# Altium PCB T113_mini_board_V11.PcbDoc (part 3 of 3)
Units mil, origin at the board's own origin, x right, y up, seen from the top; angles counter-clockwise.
Board outline 2716.54 x 2716.54 mil, 4 copper layers (Top Layer, GND, PWR, Bottom Layer); 97 components, 127 nets, 497 pads, 287 vias.
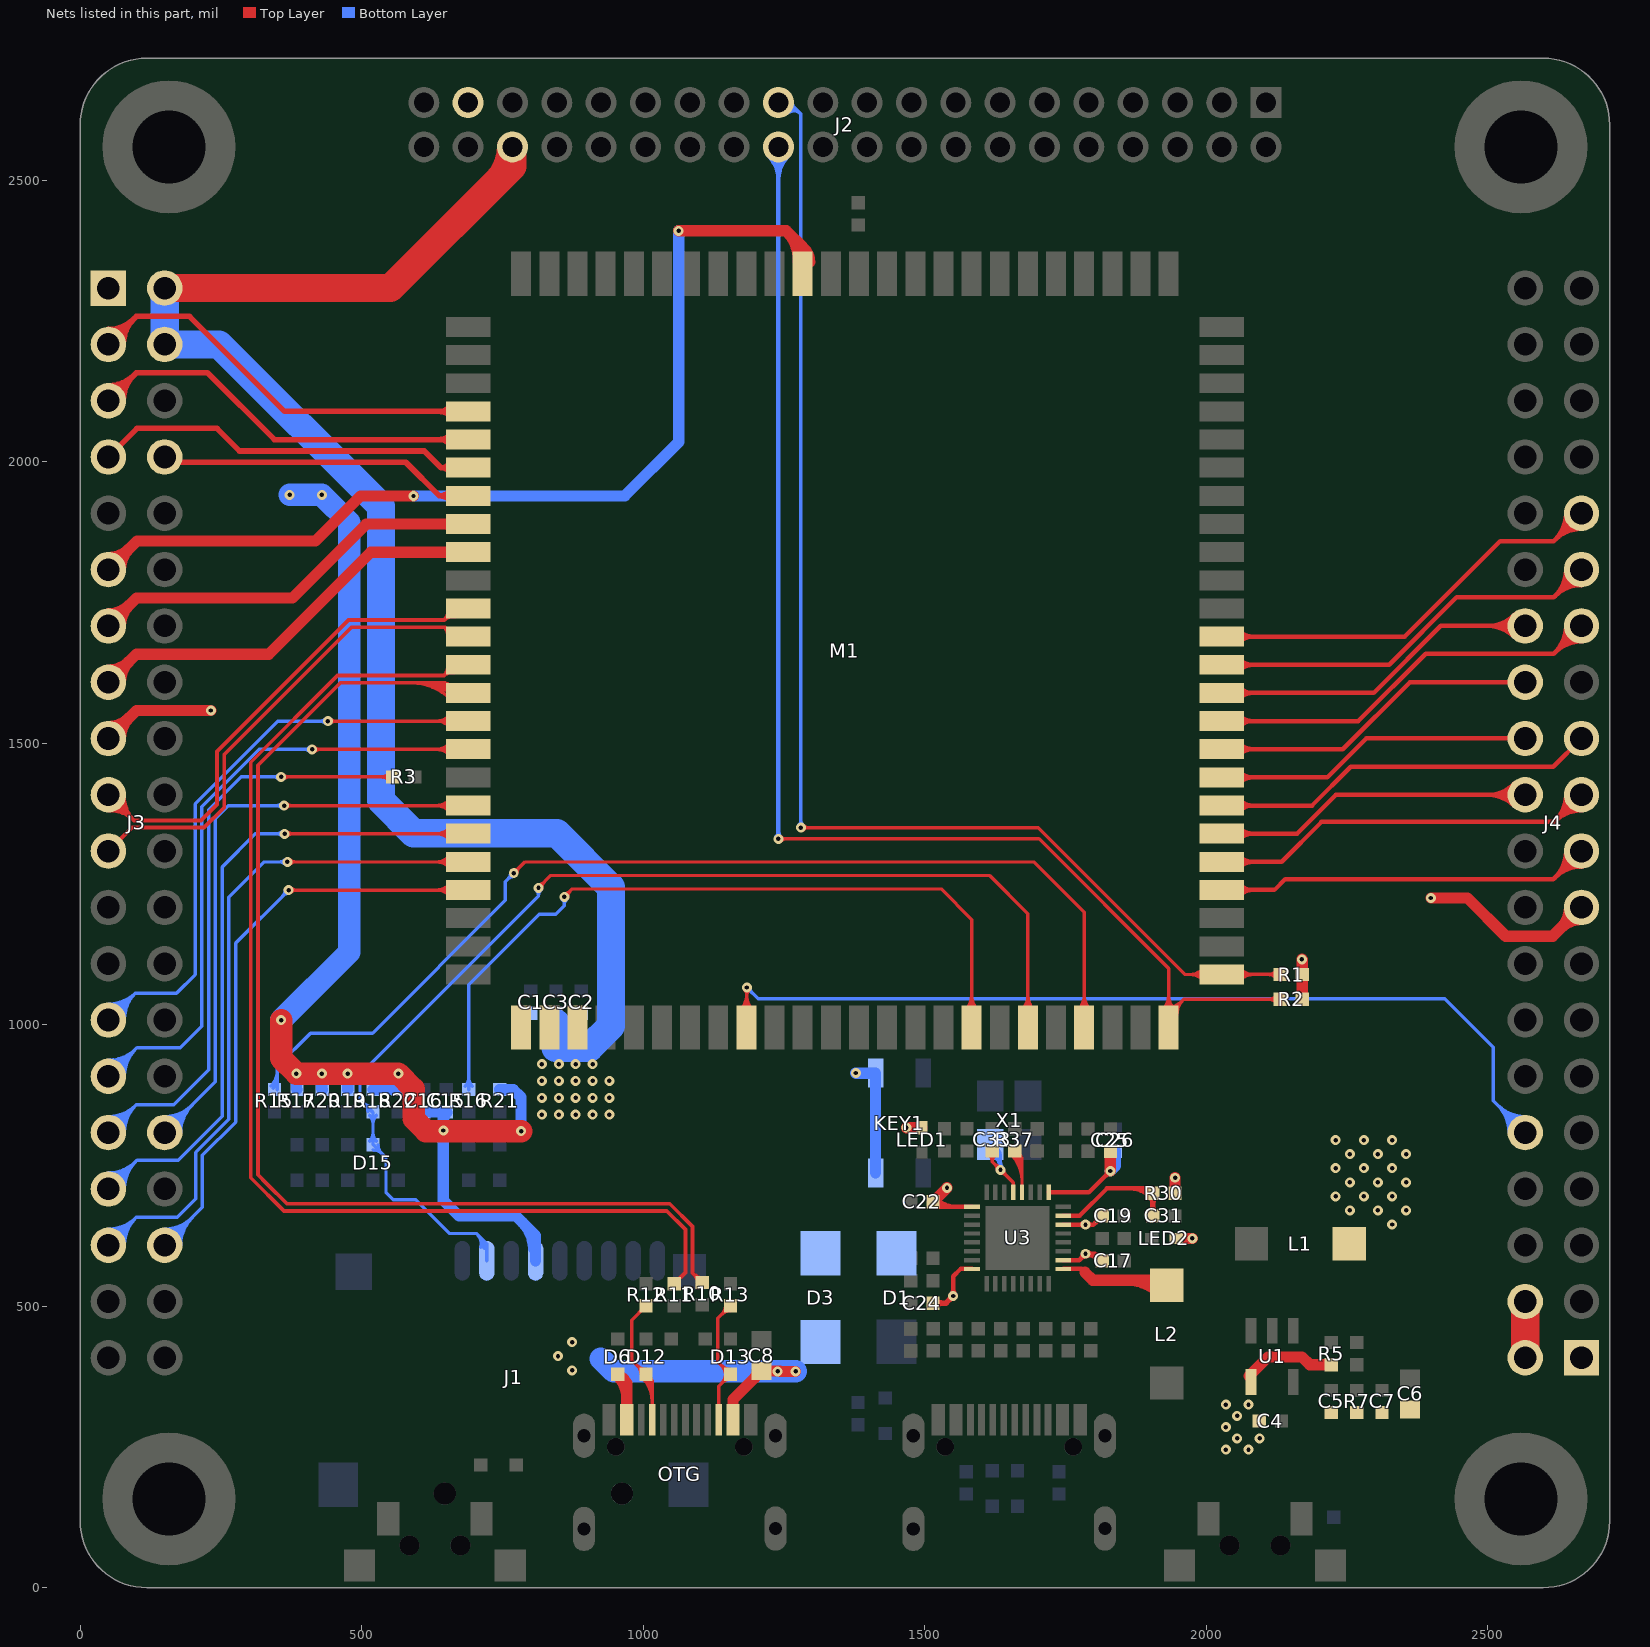
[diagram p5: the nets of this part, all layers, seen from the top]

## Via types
v1: diameter 17.72, hole 7.87, Top Layer to Bottom Layer, tented both sides, 278 vias
v2: diameter 23.62, hole 11.81, Top Layer to Bottom Layer, tented both sides, 9 vias

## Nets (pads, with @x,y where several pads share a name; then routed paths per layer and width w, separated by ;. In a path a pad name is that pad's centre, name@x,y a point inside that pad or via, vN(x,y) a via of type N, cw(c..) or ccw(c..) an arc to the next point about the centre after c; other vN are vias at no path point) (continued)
PE0: J4.29 M1.36 | length 939.2
  Top Layer w8: M1.36@2027.56,1639.21 2324.84,1639.21 2444.63,1759 2617.27,1759 J4.29@2666.54,1808.27 ; M1.36@2058.91,1629.51 cw(c2082.33,1606.1) 2082.33,1639.21 cw(c2082.33,1672.33) M1.36@2058.91,1648.91 ; J4.29@2639.04,1808.27 cw(c2572.66,1808.27) 2619.6,1761.33 cw(c2666.54,1714.39) J4.29@2666.54,1780.77 ; J4.29@2647.04,1808.27 cw(c2599.97,1808.27) 2633.25,1774.99 cw(c2666.54,1741.7) J4.29@2666.54,1788.77
PE1: J4.31 M1.37 | length 959.9
  Top Layer w8: M1.37@2027.56,1689.21 2352.21,1689.21 2522,1859 2617.27,1859 J4.31@2666.54,1908.27 ; M1.37@2058.91,1679.51 cw(c2082.33,1656.1) 2082.33,1689.21 cw(c2082.33,1722.33) M1.37@2058.91,1698.91 ; J4.31@2639.04,1908.27 cw(c2572.66,1908.27) 2619.6,1861.33 cw(c2666.54,1814.39) J4.31@2666.54,1880.77 ; J4.31@2647.04,1908.27 cw(c2599.97,1908.27) 2633.25,1874.99 cw(c2666.54,1841.7) J4.31@2666.54,1888.77
PE4: J4.28 M1.35 | length 818.5
  Top Layer w8: M1.35@2027.56,1589.21 2297.47,1589.21 2416.52,1708.27 J4.28@2566.54,1708.27 ; M1.35@2058.91,1579.51 cw(c2082.33,1556.1) 2082.33,1589.21 cw(c2082.33,1622.33) M1.35@2058.91,1598.91 ; J4.28@2547.09,1688.83 ccw(c2500.15,1641.89) 2500.15,1708.27 ccw(c2500.15,1774.65) J4.28@2547.09,1727.71 ; J4.28@2552.75,1694.48 ccw(c2519.47,1661.2) 2519.47,1708.27 ccw(c2519.47,1755.34) J4.28@2552.75,1722.05
PE5: J4.27 M1.34 | length 939.2
  Top Layer w8: M1.34@2027.56,1539.21 2270.09,1539.21 2389.88,1659 2617.27,1659 J4.27@2666.54,1708.27 ; M1.34@2058.91,1529.51 cw(c2082.33,1506.1) 2082.33,1539.21 cw(c2082.33,1572.33) M1.34@2058.91,1548.91 ; J4.27@2639.04,1708.27 cw(c2572.66,1708.27) 2619.6,1661.33 cw(c2666.54,1614.39) J4.27@2666.54,1680.77 ; J4.27@2647.04,1708.27 cw(c2599.97,1708.27) 2633.25,1674.99 cw(c2666.54,1641.7) J4.27@2666.54,1688.77
PE6: J4.26 M1.33 | length 640.3
  Top Layer w8: M1.33@2027.56,1489.21 2242.72,1489.21 2361.78,1608.27 J4.26@2566.54,1608.27 ; M1.33@2058.91,1479.51 cw(c2082.33,1456.1) 2082.33,1489.21 cw(c2082.33,1522.33) M1.33@2058.91,1498.91
PE7: J4.24 M1.32 | length 619.6
  Top Layer w8: M1.32@2027.56,1439.21 2215.35,1439.21 2284.4,1508.27 J4.24@2566.54,1508.27 ; M1.32@2058.91,1429.51 cw(c2082.33,1406.1) 2082.33,1439.21 cw(c2082.33,1472.33) M1.32@2058.91,1448.91
PE8: J4.23 M1.31 | length 740.3
  Top Layer w8: M1.31@2027.56,1389.21 2187.98,1389.21 2256.76,1458 2616.27,1458 J4.23@2666.54,1508.27 ; M1.31@2058.91,1379.51 cw(c2082.33,1356.1) 2082.33,1389.21 cw(c2082.33,1422.33) M1.31@2058.91,1398.91
PE9: J4.22 M1.30 | length 797.8
  Top Layer w8: M1.30@2027.56,1339.21 2161.21,1339.21 2230,1408 2566.27,1408 J4.22@2566.54,1408.27 ; M1.30@2058.91,1329.51 cw(c2082.33,1306.1) 2082.33,1339.21 cw(c2082.33,1372.33) M1.30@2058.91,1348.91 ; 2499.51,1408 ccw(c2499.51,1475.3) J4.22@2547.09,1427.71 ; 2500.8,1408 cw(c2500.8,1342.53) J4.22@2547.09,1388.83 ; 2518.82,1408 ccw(c2518.82,1455.98) J4.22@2552.75,1422.05 ; 2520.11,1408 cw(c2520.11,1361.85) J4.22@2552.75,1394.48
PE10: J4.21 M1.29 | length 918.5
  Top Layer w8: M1.29@2027.56,1289.21 2133.84,1289.21 2204.63,1360 2618.27,1360 J4.21@2666.54,1408.27 ; M1.29@2058.91,1279.51 cw(c2082.33,1256.1) 2082.33,1289.21 cw(c2082.33,1322.33) M1.29@2058.91,1298.91 ; J4.21@2639.04,1408.27 cw(c2572.66,1408.27) 2619.6,1361.33 cw(c2666.54,1314.39) J4.21@2666.54,1380.77 ; J4.21@2647.04,1408.27 cw(c2599.97,1408.27) 2633.25,1374.99 cw(c2666.54,1341.7) J4.21@2666.54,1388.77
PE11: J4.19 M1.28 | length 897.8
  Top Layer w8: M1.28@2027.56,1239.21 2121.21,1239.21 2140,1258 2616.27,1258 J4.19@2666.54,1308.27 ; M1.28@2058.91,1229.51 cw(c2082.33,1206.1) 2082.33,1239.21 cw(c2082.33,1272.33) M1.28@2058.91,1248.91 ; J4.19@2639.04,1308.27 cw(c2572.66,1308.27) 2619.6,1261.33 cw(c2666.54,1214.39) J4.19@2666.54,1280.77 ; J4.19@2647.04,1308.27 cw(c2599.97,1308.27) 2633.25,1274.99 cw(c2666.54,1241.7) J4.19@2666.54,1288.77
PE12: J2.23 M1.25 R1.1 | length 2625.3
  Top Layer w6: v1(1280,1350) 1702,1350 1963,1089 M1.25@2027.56,1089 ; v1@1284.14,1345.86 cw(c1294.14,1335.86) 1294.14,1350 cw(c1294.14,1364.14) v1@1284.14,1354.14 ; 1969.86,1089 ccw(c1969.86,1125.25) M1.25@1995.5,1099.62 ; 1970.89,1089 cw(c1970.89,1054.2) M1.25@1995.5,1078.81 ; 1984.35,1089 ccw(c1984.35,1110.77) M1.25@1999.74,1095.38 ; 1985.38,1089 cw(c1985.38,1068.68) M1.25@1999.74,1083.05 ; M1.25@2027.56,1089.21 2131.1,1089.21 R1.1@2131.32,1089 ; M1.25@2055.38,1083.05 cw(c2070.26,1068.17) 2070.26,1089.21 cw(c2070.26,1110.26) M1.25@2055.38,1095.38 ; M1.25@2059.62,1078.81 cw(c2084.74,1053.68) 2084.74,1089.21 cw(c2084.74,1124.74) M1.25@2059.62,1099.62 ; 2109.53,1089.21 cw(c2109.53,1067.22) R1.1@2125.08,1082.77 ; 2110.56,1089.21 ccw(c2110.56,1109.76) R1.1@2125.08,1095.23
  Bottom Layer w6: J2.23@1240.16,2657.48 1280,2617.64 ; J2.23@1248.13,2628.09 cw(c1258.78,2615.13) 1270.64,2626.99 ; J2.23@1251.94,2623.46 cw(c1263,2609.99) 1275.32,2622.31 ; J2.23@1255.75,2618.82 cw(c1267.22,2604.86) 1280,2617.64 ; J2.23@1264.71,2637.8 ccw(c1276.48,2637.8) 1268.16,2629.47 ; v1@1275.86,1354.14 ccw(c1265.86,1364.14) 1280,1364.14 ccw(c1294.14,1364.14) v1@1284.14,1354.14 ; v1(1280,1350) 1280,2617.64
PE13: J2.24 M1.24 R2.1 | length 2751.4
  Top Layer w6: v1(1240,1330) 1703,1330 1933.27,1099.73 M1.24@1933.27,1018.27 ; v1@1244.14,1325.86 cw(c1254.14,1315.86) 1254.14,1330 cw(c1254.14,1344.14) v1@1244.14,1334.14 ; M1.24@1922.86,1026.98 ccw(c1897.74,1052.1) 1933.27,1052.1 ccw(c1968.8,1052.1) M1.24@1943.67,1026.98 ; M1.24@1927.1,1022.74 ccw(c1912.22,1037.62) 1933.27,1037.62 ccw(c1954.31,1037.62) M1.24@1939.43,1022.74 ; M1.24@1933.27,994.92 M1.24@1933.27,1018.27 ; M1.24@1933.27,1025.29 ccw(c1933.27,1042.25) M1.24@1945.26,1030.26 ; M1.24@1933.27,1031.29 ccw(c1933.27,1062.73) 1955.5,1040.5 ; M1.24@1941.98,1016.57 cw(c1967.11,1016.57) 1949.34,1034.34 ; M1.24@1947.98,1016.57 cw(c1987.6,1016.57) 1959.59,1044.59 ; R2.1@2125.08,1038.77 ccw(c2110.04,1023.73) 2110.04,1045 ccw(c2110.04,1066.27) R2.1@2125.08,1051.23 ; R2.1@2131.32,1045 1960,1045 M1.24@1933.27,1018.27
  Bottom Layer w8: J2.24@1223.5,2542.4 cw(c1183.28,2502.18) 1240.16,2502.18 cw(c1297.03,2502.18) J2.24@1256.81,2542.4 ; J2.24@1229.15,2548.05 cw(c1202.59,2521.49) 1240.16,2521.49 cw(c1277.72,2521.49) J2.24@1251.16,2548.05 ; v1@1236.56,1333.44 ccw(c1227.9,1342.1) 1240.16,1342.1 ; v1@1240.16,1330 J2.24@1240.16,2578.74 ; 1240.16,1341.35 ccw(c1251.35,1341.35) v1@1243.44,1333.44
PU_CHIP: C31.2 R30.2 U3.15 | length 336.3
  Top Layer w8: U3.15@1745.91,660.52 1775.02,660.52 1823.58,709.09 1896.45,709.09 R30.2@1905.24,700.3 ; 1865.16,709.09 cw(c1865.16,660.23) R30.2@1899.71,694.78 ; 1884.48,709.09 cw(c1884.48,679.54) R30.2@1905.37,700.44
  Top Layer w10: C31.2@1900.42,665.12 ccw(c1888.79,676.75) 1905.24,676.75 ccw(c1921.68,676.75) C31.2@1910.05,665.12 ; R30.2@1900.42,695.49 cw(c1888.79,683.86) 1905.24,683.86 cw(c1921.68,683.86) R30.2@1910.05,695.49 ; C31.2@1905.24,660.3 R30.2@1905.24,700.3
SD_CLK: M1.17 R16.2 | length 1540.4
  Top Layer w6: v1(860,1227) 874,1241 1529,1241 1583.27,1186.73 M1.17@1583.27,994.92 ; v1@860,1232.86 ccw(c860,1247) 870,1237 ccw(c880,1227) v1@865.86,1227 ; M1.17@1572.86,1026.98 ccw(c1547.74,1052.1) 1583.27,1052.1 ccw(c1618.8,1052.1) M1.17@1593.67,1026.98 ; M1.17@1577.1,1022.74 ccw(c1562.22,1037.62) 1583.27,1037.62 ccw(c1604.31,1037.62) M1.17@1589.43,1022.74
  Bottom Layer w6: R16.2@683.77,890.92 ccw(c668.73,905.96) 690,905.96 ccw(c711.27,905.96) R16.2@696.23,890.92 ; R16.2@690,884.69 690,1070.97 815.03,1196 845,1196 860,1211 v1(860,1227) ; v1@855.86,1222.86 cw(c845.86,1212.86) 860,1212.86 cw(c874.14,1212.86) v1@864.14,1222.86
SD_D3: D15.2 J1.2 M1.19 R18.2 | length 2359.7
  Top Layer w6: v1(814,1243) 836,1265 1615,1265 1683.27,1196.73 M1.19@1683.27,994.92 ; v1@814,1248.86 ccw(c814,1263) 824,1253 ccw(c834,1243) v1@819.86,1243 ; M1.19@1672.86,1026.98 ccw(c1647.74,1052.1) 1683.27,1052.1 ccw(c1718.8,1052.1) M1.19@1693.67,1026.98 ; M1.19@1677.1,1022.74 ccw(c1662.22,1037.62) 1683.27,1037.62 ccw(c1704.31,1037.62) M1.19@1689.43,1022.74
  Bottom Layer w6: 502.67,861.3 ccw(c520,878.63) R18.2@520,854.13 ; 505.91,858.07 cw(c493.15,845.31) R18.2@511.19,845.31 ; D15.2@513.77,792.73 ccw(c498.73,807.77) 520,807.77 ccw(c541.27,807.77) D15.2@526.23,792.73 ; R18.2@513.77,839.08 cw(c498.73,824.04) 520,824.04 cw(c541.27,824.04) R18.2@526.23,839.08 ; D15.2@520,777.68 cw(c520,755.08) 535.98,771.06 ; D15.2@520,786.5 520,843.98 497,866.98 497,911.91 814,1228.91 ; D15.2@521.34,786.5 521.34,785.71 543,764.05 543,702 556,689 596.03,689 656.03,629 704,629 ; D15.2@528.81,786.5 ccw(c548.75,786.5) 534.65,772.4 ; J1.2@711.55,604.27 ccw(c684.55,609.55) 704,629 ; 711.97,621.03 cw(c697.89,606.94) J1.2@717.44,603.12 ; J1.2@722.13,580.55 722.13,610.87 704,629 ; v1@809.87,1238.85 cw(c799.99,1228.91) 814,1228.91 ; v1(814,1243) 814,1228.91 ; v1@818.13,1238.85 ccw(c828.01,1228.91) 814,1228.91
SD_DET: M1.21 R15.2 | length 2068.3
  Top Layer w6: v1(770,1269) 790,1289 1694,1289 1783.27,1199.73 M1.21@1783.27,994.92 ; v1@770,1274.86 ccw(c770,1289) 780,1279 ccw(c790,1269) v1@775.86,1269 ; M1.21@1772.86,1026.98 ccw(c1747.74,1052.1) 1783.27,1052.1 ccw(c1818.8,1052.1) M1.21@1793.67,1026.98 ; M1.21@1777.1,1022.74 ccw(c1762.22,1037.62) 1783.27,1037.62 ccw(c1804.31,1037.62) M1.21@1789.43,1022.74
  Bottom Layer w6: R15.2@338.77,890.92 ccw(c311.66,918.03) 350,918.03 ; R15.2@343.01,886.67 ccw(c326.14,903.54) 350,903.54 ; R15.2@350,884.69 350,926 409,985 519.18,985 755,1220.82 755,1254 v1(770,1269) ; v1@764.14,1269 cw(c750,1269) 760,1259 cw(c770,1249) v1@770,1263.14
SDIO_CLK: J3.31 R3.1 | length 1371.4
  Top Layer w6: v1(357,1440) R3.1@555.32,1440 ; v1@361.14,1435.86 cw(c371.14,1425.86) 371.14,1440 cw(c371.14,1454.14) v1@361.14,1444.14 ; R3.1@549.08,1433.77 ccw(c534.04,1418.73) 534.04,1440 ccw(c534.04,1461.27) R3.1@549.08,1446.23
  Bottom Layer w6: J3.31@50,808.27 99.73,858 166,858 228,920 228,1382.06 285.94,1440 v1(357,1440) ; J3.31@50,824.76 ccw(c50,864.59) 78.16,836.43 ccw(c106.32,808.27) J3.31@66.5,808.27 ; J3.31@50,830.76 ccw(c50,885.07) 88.4,846.67 ccw(c126.81,808.27) J3.31@72.5,808.27 ; J3.31@50,836.76 ccw(c50,905.56) 98.65,856.91 ccw(c147.29,808.27) J3.31@78.5,808.27 ; v1@352.86,1435.86 ccw(c342.86,1425.86) 342.86,1440 ccw(c342.86,1454.14) v1@352.86,1444.14
SDIO_CMD: J3.27 M1.87 | length 1418.2
  Top Layer w6: v1@440,1539.21 M1.87@688.98,1539.21 ; v1@444.14,1534.86 cw(c454.66,1524.34) 454.66,1539.21 ; v1@444.14,1543.14 ccw(c453.63,1552.63) 453.63,1539.21 ; M1.87@656.92,1528.81 ccw(c631.79,1503.68) 631.79,1539.21 ccw(c631.79,1574.74) M1.87@656.92,1549.62 ; M1.87@661.16,1533.05 ccw(c646.28,1518.17) 646.28,1539.21 ccw(c646.28,1560.26) M1.87@661.16,1545.38
  Bottom Layer w6: J3.27@50,1008.27 97.73,1056 ; J3.27@50.22,1024.76 ccw(c50.74,1062.79) 77.63,1035.9 ccw(c104.52,1009.01) J3.27@66.49,1008.49 ; J3.27@50.3,1030.76 ccw(c51.01,1082.62) 87.68,1045.95 ccw(c124.35,1009.27) J3.27@72.49,1008.57 ; J3.27@50.39,1036.76 ccw(c51.27,1102.45) 97.73,1056 ; J3.27@78.49,1008.65 cw(c144.19,1009.54) 97.73,1056 ; v1@435.86,1534.86 ccw(c425.86,1524.86) 425.86,1539 ccw(c425.86,1553.14) v1@435.86,1543.14 ; v1(440,1539) 351,1539 204,1392 204,1089 171,1056 97.73,1056
SDIO_D0: J3.29 M1.88 | length 1497.3
  Top Layer w6: v1(412,1489) 688.76,1489 M1.88@688.98,1489.21 ; v1@416.14,1484.86 cw(c426.14,1474.86) 426.14,1489 cw(c426.14,1503.14) v1@416.14,1493.14 ; 631.28,1489 ccw(c631.28,1525.25) M1.88@656.92,1499.62 ; 632.31,1489 cw(c632.31,1454.2) M1.88@656.92,1478.81 ; 645.77,1489 ccw(c645.77,1510.77) M1.88@661.16,1495.38 ; 646.79,1489 cw(c646.79,1468.68) M1.88@661.16,1483.05
  Bottom Layer w6: J3.29@50,908.27 100.73,959 178,959 216,997 216,1387.03 317.97,1489 v1(412,1489) ; J3.29@50,924.76 ccw(c50,964.59) 78.16,936.43 ccw(c106.32,908.27) J3.29@66.5,908.27 ; J3.29@50,930.76 ccw(c50,985.07) 88.4,946.67 ccw(c126.81,908.27) J3.29@72.5,908.27 ; J3.29@50,936.76 ccw(c50,1005.56) 98.65,956.91 ccw(c147.29,908.27) J3.29@78.5,908.27 ; v1@407.86,1484.86 ccw(c397.86,1474.86) 397.86,1489 ccw(c397.86,1503.14) v1@407.86,1493.14
SDIO_D1: J3.32 M1.90 | length 1442.8
  Top Layer w6: v1(362,1389) 688.76,1389 M1.90@688.98,1389.21 ; v1@366.14,1384.86 cw(c376.14,1374.86) 376.14,1389 cw(c376.14,1403.14) v1@366.14,1393.14 ; 631.28,1389 ccw(c631.28,1425.25) M1.90@656.92,1399.62 ; 632.31,1389 cw(c632.31,1354.2) M1.90@656.92,1378.81 ; 645.77,1389 ccw(c645.77,1410.77) M1.90@661.16,1395.38 ; 646.79,1389 cw(c646.79,1368.68) M1.90@661.16,1383.05
  Bottom Layer w6: J3.32@150,808.27 240,898.27 240,1366 263,1389 v1(362,1389) ; J3.32@150,824.76 ccw(c150,864.59) 178.16,836.43 ccw(c206.32,808.27) J3.32@166.5,808.27 ; J3.32@150,830.76 ccw(c150,885.07) 188.4,846.67 ccw(c226.81,808.27) J3.32@172.5,808.27 ; J3.32@150,836.76 ccw(c150,905.56) 198.65,856.91 ccw(c247.29,808.27) J3.32@178.5,808.27 ; v1@357.86,1384.86 ccw(c347.86,1374.86) 347.86,1389 ccw(c347.86,1403.14) v1@357.86,1393.14
SDIO_D2: J3.35 M1.92 | length 1589.1
  Top Layer w6: v1(368,1289) 688.76,1289 M1.92@688.98,1289.21 ; v1@372.14,1284.86 cw(c382.14,1274.86) 382.14,1289 cw(c382.14,1303.14) v1@372.14,1293.14 ; 631.28,1289 ccw(c631.28,1325.25) M1.92@656.92,1299.62 ; 632.31,1289 cw(c632.31,1254.2) M1.92@656.92,1278.81 ; 645.77,1289 ccw(c645.77,1310.77) M1.92@661.16,1295.38 ; 646.79,1289 cw(c646.79,1268.68) M1.92@661.16,1283.05
  Bottom Layer w6: J3.35@50,608.27 99.73,658 172,658 205,691 205,773.03 264,832.03 264,1226 327,1289 v1(368,1289) ; J3.35@50,624.76 ccw(c50,664.59) 78.16,636.43 ccw(c106.32,608.27) J3.35@66.5,608.27 ; J3.35@50,630.76 ccw(c50,685.07) 88.4,646.67 ccw(c126.81,608.27) J3.35@72.5,608.27 ; J3.35@50,636.76 ccw(c50,705.56) 98.65,656.91 ccw(c147.29,608.27) J3.35@78.5,608.27 ; v1@363.86,1284.86 ccw(c353.86,1274.86) 353.86,1289 ccw(c353.86,1303.14) v1@363.86,1293.14
SDIO_D3: J3.33 M1.91 | length 1549.1
  Top Layer w6: v1(363,1339) 688.76,1339 M1.91@688.98,1339.21 ; v1@367.14,1334.86 cw(c377.14,1324.86) 377.14,1339 cw(c377.14,1353.14) v1@367.14,1343.14 ; 631.28,1339 ccw(c631.28,1375.25) M1.91@656.92,1349.62 ; 632.31,1339 cw(c632.31,1304.2) M1.91@656.92,1328.81 ; 645.77,1339 ccw(c645.77,1360.77) M1.91@661.16,1345.38 ; 646.79,1339 cw(c646.79,1318.68) M1.91@661.16,1333.05
  Bottom Layer w6: J3.33@50,708.27 100.73,759 174,759 252,837 252,1280 311,1339 v1(363,1339) ; J3.33@50,724.76 ccw(c50,764.59) 78.16,736.43 ccw(c106.32,708.27) J3.33@66.5,708.27 ; J3.33@50,730.76 ccw(c50,785.07) 88.4,746.67 ccw(c126.81,708.27) J3.33@72.5,708.27 ; J3.33@50,736.76 ccw(c50,805.56) 98.65,756.91 ccw(c147.29,708.27) J3.33@78.5,708.27 ; v1@358.86,1334.86 ccw(c348.86,1324.86) 348.86,1339 ccw(c348.86,1353.14) v1@358.86,1343.14
SW_DCDC: L2.2 U3.9 | length 257.7
  Top Layer w8: U3.9@1745.91,566.03 1778.64,566.03 1784.58,560.09
  Top Layer w20: 1784.58,560.09 1798.58,546.09 1920.75,546.09 L2.2@1929.92,536.92 ; 1860.64,546.09 cw(c1860.64,467.64) L2.2@1916.11,523.11
SYS_3V3: C5.2 C6.2 C7.2 C15.1 C16.1 C17.2 C19.2 C22.2 C24.2 C25.2 C26.2 J1.4 J2.37 J3.1 J3.17 J4.1 J4.17 KEY1.3 KEY1.4 L1.2 LED1.1 LED2.1 R1.2 R2.2 R7.1 R17.1 R18.1 R19.1 R20.1 R21.1 R22.1 R30.1 U3.10 U3.14 U3.17 U3.25 U3.32 | length 4369.3
  Top Layer w8: C22.2@1514.47,685.17 ccw(c1535.95,706.65) 1535.95,676.27 ; C22.2@1514.61,685.3 1523.64,676.27 U3.25@1583.94,676.27 ; C22.2@1520.13,690.83 ccw(c1555.26,725.96) 1555.26,676.27 ; v1@1547.15,521.53 ccw(c1538.85,529.82) 1550.58,529.82 ccw(c1562.31,529.82) v1@1554.02,521.53 ; v1(1550.58,518.09) 1550.58,553.09 1563.53,566.03 U3.32@1583.94,566.03 ; U3.17@1720.04,702.13 1791.62,702.13 v1(1829.58,740.09) ; U3.10@1745.91,581.78 1774.28,581.78 v1(1785.58,593.09) ; U3.14@1745.91,644.77 v1(1785.58,644.77) 1799.71,644.77 C19.2@1815.24,660.3 ; v1@1780.72,593.09 cw(c1769,593.09) 1777.29,584.8 cw(c1785.58,576.5) v1@1785.58,588.23 ; v1@1782.15,641.34 ccw(c1773.85,633.04) 1773.85,644.77 ccw(c1773.85,656.5) v1@1782.15,648.21 ; v1@1788.01,588.88 cw(c1793.88,578.72) 1796.91,590.05 cw(c1799.95,601.38) v1@1789.79,595.52 ; v1@1789.02,589.65 cw(c1797.31,581.36) 1797.31,593.09 cw(c1797.31,604.82) v1@1789.02,596.53 ; v1@1789.02,641.34 cw(c1797.31,633.04) 1797.31,644.77 cw(c1797.31,656.5) v1@1789.02,648.21 ; 1797.1,593.09 cw(c1797.1,573.55) C17.2@1815.41,580.37 ; C17.2@1807.43,580.54 ccw(c1790.41,581.05) 1802.45,593.09 ; C19.2@1807.42,660.3 cw(c1788.57,660.3) 1801.9,646.97 cw(c1815.24,633.63) C19.2@1815.24,652.49 ; C17.2@1807.92,577.58 ccw(c1785.58,569.26) v1(1785.58,593.09) ; C17.2@1815,588.11 cw(c1814.49,605.13) 1802.45,593.09 ; C17.2@1815.24,580.3 1802.45,593.09 ; v1@1824.72,740.09 cw(c1813,740.09) 1821.29,731.8 cw(c1829.58,723.5) v1@1829.58,735.23 ; v1(1785.58,593.09) 1802.45,593.09
  Top Layer w10: C24.2@1514.61,505.3 1537.8,505.3 v1(1550.58,518.09) ; C24.2@1519.42,500.49 cw(c1531.05,488.86) 1531.05,505.3 cw(c1531.05,521.75) C24.2@1519.42,510.12 ; v1@1546.72,518.09 cw(c1537.41,518.09) 1544,511.5 cw(c1550.58,504.92) v1@1550.58,514.23
  Top Layer w20: J3.17@50,1508.27 99.73,1558 v1(232,1558) ; J3.17@50,1529.76 ccw(c50,1581.66) 86.7,1544.96 ccw(c123.39,1508.27) J3.17@71.5,1508.27 ; v1(1467.58,817.09) 1467.72,816.96 LED1.1@1494.92,816.96 ; C22.2@1514.61,685.3 1539.39,710.09 v1(1539.58,710.09) ; v1(1829.58,740.09) 1829.58,774.96 C25.2@1829.92,775.3 ; R30.1@1944.61,700.3 v1@1944.61,728.07 ; LED2.1@1946.58,620.3 v1(1975.37,620.3) v1@1975.58,620.09 ; v1(2170,1116) 2170.69,1115.31 R1.2@2170.69,1089 R2.2@2170.69,1045 ; v1(2399,1225) 2464,1225 2532,1157 2615.27,1157 J4.17@2666.54,1208.27 ; J4.17@2645.04,1208.27 cw(c2593.14,1208.27) 2629.84,1171.57 cw(c2666.54,1134.88) J4.17@2666.54,1186.77
  Top Layer w40: v1(357,1008) 357,940 v1(384,913) v1(429,913) v1(475,913) v1(565,913) 592,886 592,833 614,811 v1(783,811)
  Bottom Layer w20: v1(384,913) 384,885.68 R17.1@385,884.68 ; v1(429,913) 429,885.68 R20.1@430,884.68 ; R19.1@475,884.68 v1(475,913) ; R18.1@520,884.68 R22.1@565,884.68 v1(565,913) ; C16.1@610,845.31 C15.1@645,845.31 ; 645,828.87 cw(c666.44,828.87) C15.1@651.28,844.03 ; C15.1@650,845.31 645,840.31 v1(645,812) 645,688 673,660 774,660 808.74,625.26 J1.4@808.74,580.55 ; R21.1@745,884.68 745.32,885 769,885 783,871 v1(783,811) ; 785.98,648.02 cw(c740.18,602.21) J1.4@804.96,602.21 ; v1(1377.58,914.09) 1377.78,913.89 KEY1.4@1412.6,913.89 KEY1.3@1412.6,736.72 ; v1(1829.58,740.09) 1838.58,749.09 C26.2@1838.58,775.41
  Bottom Layer w40: v1(357,1008) 478,1129 478,1892 v1(429,1941) v1(372,1941)
  other v1: 2330,645 2255,670 2305,670 2355,670 2230,695 2280,695 2330,695 2255,720 2305,720 2355,720 1944.58,728.09 2230,745 2280,745 2330,745 2255,770 2305,770 2355,770 2230,795 2280,795 2330,795
TP_X1: J3.3 M1.76 | length 940.7
  Top Layer w10: J3.3@50,2208.27 99.73,2258 194,2258 362.79,2089.21 M1.76@688.98,2089.21 ; J3.3@50,2224.76 ccw(c50,2264.59) 78.16,2236.43 ccw(c106.32,2208.27) J3.3@66.5,2208.27 ; J3.3@50,2234.76 ccw(c50,2298.73) 95.23,2253.5 ccw(c140.46,2208.27) J3.3@76.5,2208.27 ; M1.76@658.33,2080.22 ccw(c636.62,2058.51) 636.62,2089.21 ccw(c636.62,2119.91) M1.76@658.33,2098.2
TP_X2: J3.5 M1.77 | length 920
  Top Layer w10: J3.5@50,2108.27 99.73,2158 226,2158 344.79,2039.21 M1.77@688.98,2039.21 ; J3.5@50,2124.76 ccw(c50,2164.59) 78.16,2136.43 ccw(c106.32,2108.27) J3.5@66.5,2108.27 ; J3.5@50,2134.76 ccw(c50,2198.73) 95.23,2153.5 ccw(c140.46,2108.27) J3.5@76.5,2108.27 ; M1.77@658.33,2030.22 ccw(c636.62,2008.51) 636.62,2039.21 ccw(c636.62,2069.91) M1.77@658.33,2048.2
TP_Y1: J3.7 M1.78 | length 727
  Top Layer w10: J3.7@50,2008.27 100.73,2059 243,2059 283,2019 611,2019 640.79,1989.21 ; M1.78@657.41,1981.25 ccw(c640.79,1967.89) 640.79,1989.21 ; M1.78@657.41,1997.18 cw(c640.79,2010.54) 640.79,1989.21 ; M1.78@688.98,1989.21 640.79,1989.21
TP_Y2: J3.8 M1.79 | length 596.5
  Top Layer w10: J3.8@150,2008.27 159.27,1999 578.21,1999 638,1939.21 ; M1.79@658.04,1930.52 ccw(c638,1911.77) 638,1939.21 ; M1.79@658.04,1947.9 cw(c638,1966.66) 638,1939.21 ; M1.79@673,1939.21 638,1939.21
TVIN0: J3.13 M1.80 | length 824.7
  Top Layer w20: J3.13@50,1708.27 99.73,1758 377,1758 508.21,1889.21 M1.80@688.98,1889.21 ; J3.13@50,1729.76 ccw(c50,1781.66) 86.7,1744.96 ccw(c123.39,1708.27) J3.13@71.5,1708.27 ; M1.80@661.87,1883.76 ccw(c648.69,1870.58) 648.69,1889.21 ccw(c648.69,1907.84) M1.80@661.87,1894.67
TVIN1: J3.15 M1.81 | length 845.4
  Top Layer w20: J3.15@50,1608.27 99.73,1658 335,1658 516.21,1839.21 M1.81@688.98,1839.21 ; J3.15@50,1629.76 ccw(c50,1681.66) 86.7,1644.96 ccw(c123.39,1608.27) J3.15@71.5,1608.27 ; M1.81@661.87,1833.76 ccw(c648.69,1820.58) 648.69,1839.21 ccw(c648.69,1857.84) M1.81@661.87,1844.67
TVOUT: J3.11 M1.62 | length 1957.7
  Top Layer w20: J3.11@50,1808.27 100.73,1859 418,1859 498,1939 v1(592,1939) ; J3.11@50,1829.76 ccw(c50,1881.66) 86.7,1844.96 ccw(c123.39,1808.27) J3.11@71.5,1808.27 ; v1(1063,2410) 1254,2410 ; M1.62@1275.56,2355.41 ccw(c1201.87,2357.86) 1254,2410 ; M1.62@1277.81,2360.61 ccw(c1264.64,2373.79) 1283.27,2373.79 ccw(c1301.9,2373.79) M1.62@1288.72,2360.61 ; M1.62@1283.27,2333.5 1283.27,2380.73 1254,2410 ; 1286.6,2377.4 cw(c1264.97,2355.77) M1.62@1295.54,2354.75
  Bottom Layer w20: v1(592,1939) 967,1939 1063,2035 v1(1063,2410)
TYPEC_CC1: D12.2 OTG.A5 R12.2 | length 376.7
  Top Layer w6: D12.2@996.11,378.81 ccw(c974.84,378.81) 989.88,393.85 ccw(c1004.92,408.89) D12.2@1004.92,387.62 ; D12.2@998.69,372.58 cw(c957.13,331.02) 1015.91,331.02 ; D12.2@1002.93,376.82 cw(c971.62,345.5) 1015.91,345.5 ; R12.2@1004.92,500.62 979.58,475.28 979.58,404.15 D12.2@1004.92,378.81 1015.91,367.82 OTG.A5@1015.91,298.22 ; D12.2@1007.18,381.06 cw(c986.1,359.99) 1015.91,359.99 ; OTG.A5@1013.85,322.71 ccw(c1008.89,327.67) 1015.91,327.67 ccw(c1022.92,327.67) OTG.A5@1017.96,322.71
TYPEC_CC2: D13.2 OTG.B5 R13.2 | length 340.8
  Top Layer w6: OTG.B5@1131.96,322.71 ccw(c1127,327.67) 1134.02,327.67 ccw(c1141.03,327.67) OTG.B5@1136.07,322.71 ; OTG.B5@1134.02,298.22 1134.02,357.9 D13.2@1154.92,378.81 1132.58,401.15 1132.58,478.28 R13.2@1154.92,500.62 ; R13.2@1146.11,500.62 cw(c1124.84,500.62) 1139.88,485.58 cw(c1154.92,470.54) R13.2@1154.92,491.81 ; D13.2@1154.92,370 ccw(c1154.92,348.72) 1139.88,363.77 ccw(c1124.84,378.81) 1146.11,378.81 ccw(c1124.84,378.81) 1139.88,393.85 ccw(c1154.92,408.89) D13.2@1154.92,387.62
USB0_DM: M1.85 R11.2 | length 2150
  Top Layer w6.69: M1.85@652.98,1638.36 cw(c629.06,1636.95) 646,1620 ; M1.85@664.11,1625.21 ccw(c659.76,1606.24) 646,1620 ; M1.85@688.98,1639.21 665.21,1639.21 646,1620 ; R11.2@1054.92,539.99 1074.89,559.96 1074.89,636.11 1041.85,669.15 361.85,669.15 303,728 303,1466 457,1620 646,1620
USB0_DP: M1.86 R10.2 | length 2379.4
  Top Layer w6.69: 331.95,717 367.1,681.85 1047.15,681.85 1087.58,641.42 1087.58,559.16 R10.2@1104.88,541.87 ; 331.98,717.02 315.69,733.31 315.69,1460.74 462.26,1607.31 647.69,1607.31 ; 588.95,1607.31 cw(c588.95,1510.84) M1.86@657.16,1579.05 ; 605.1,1607.31 cw(c605.1,1526.99) M1.86@661.89,1583.78 ; 621.26,1607.31 cw(c621.26,1543.15) M1.86@666.63,1588.52 ; 637.42,1607.31 cw(c637.42,1559.31) M1.86@671.36,1593.25 ; M1.86@653.09,1591.2 ccw(c634.22,1593.84) 647.69,1607.31 ; M1.86@663.56,1603.08 cw(c659.27,1618.88) 647.69,1607.31 ; M1.86@688.98,1589.21 665.79,1589.21 647.69,1607.31 ; R10.2@1096.41,541.87 ccw(c1075.98,541.87) 1090.43,556.32 ccw(c1104.88,570.77) R10.2@1104.88,550.33
USB1_DM: J3.21 M1.84 | length 874.5
  Top Layer w6.69: J3.21@50,1308.27 91.73,1350 220,1350 255.69,1385.69 255.69,1479.69 481.98,1705.98 647.02,1705.98 ; M1.84@652.98,1690.14 ccw(c632.51,1691.48) 647.02,1705.98 ; M1.84@662.29,1702.67 cw(c657.23,1716.19) 647.02,1705.98 ; M1.84@663.79,1689.21 647.02,1705.98
USB1_DP: J3.19 M1.83 | length 1134.7
  Top Layer w6.69: J3.19@50,1408.27 95.57,1362.69 ; J3.19@50.56,1393.51 cw(c51.76,1362.22) 73.9,1384.37 cw(c96.04,1406.51) J3.19@64.75,1407.7 ; J3.19@50.82,1386.83 cw(c52.56,1341.35) 84.74,1373.53 cw(c116.92,1405.71) J3.19@71.44,1407.45 ; J3.19@51.08,1380.14 cw(c53.36,1320.48) 95.57,1362.7 ; J3.19@78.13,1407.19 ccw(c137.79,1404.91) 95.57,1362.7 ; M1.83@653.07,1737.39 cw(c630.81,1734.54) 646.68,1718.68 ; M1.83@665.38,1724.97 ccw(c662.37,1702.98) 646.68,1718.68 ; M1.83@688.98,1739.21 667.21,1739.21 646.68,1718.68 ; 95.57,1362.69 214.69,1362.69 243,1391 243,1484.95 476.73,1718.68 646.68,1718.68
USB_OTG_VBUS: C8.2 D3.1 D6.2 OTG.A4B9 OTG.B4A9 | length 698.5
  Top Layer w20: D6.2@953.64,377.53 cw(c912.62,336.51) 970.63,336.51 ; D6.2@954.5,377.05 cw(c949.6,356.59) 970.63,356.59 ; D6.2@954.92,378.81 970.63,363.1 OTG.A4B9@970.63,298.22 ; OTG.B4A9@1159.61,298.22 1159.61,334.35 C8.2@1209.88,384.62 1243.05,384.62 1243.58,384.09 v1(1270.58,384.09) ; C8.2@1196.7,371.45 ccw(c1183.53,384.62) C8.2@1202.16,384.62
  Bottom Layer w40: 924.92,406.56 947.39,384.09 v1(1270.58,384.09)
  other v1: 1238.58,384.09 873.58,386.09 848.58,411.09 873.58,436.09
VCC_5V: C1.2 C2.2 C3.2 C4.2 D1.2 D3.2 J2.36 J3.2 J3.4 J4.2 J4.4 M1.1 M1.2 M1.3 R5.2 U1.4 | length 3082
  Top Layer w20: U1.4@2076,376 2109.88,409.88 2170.12,409.88 2184.02,395.98 R5.2@2222.21,395.98
  Top Layer w50: J3.2@150,2308.27 551.27,2308.27 767.71,2524.71 J2.36@767.71,2559.06 ; 739.06,2496.06 ccw(c676.07,2559.06) J2.36@765.16,2559.06 ; J4.2@2566.54,408.27 J4.4@2566.54,508.27
  Bottom Layer w50: J3.2@150,2308.27 J3.4@150,2208.27 246.73,2208.27 534,1921 534,1398 592,1340 847,1340 943,1244 943,998 904,959 844,959 845,960 845,1003
  other v1: 2035,245 2075,245 2055,265 2095,265 2035,285 2055,305 2035,325 2075,325 820,840 850,840 880,840 910,840 940,840 820,870 850,870 880,870 910,870 940,870 820,900 850,900 880,900 910,900 940,900 820,930 850,930 880,930 910,930
WL_REG_ON: J3.36 M1.93 | length 1430.1
  Top Layer w6: v1(370,1239) 688.76,1239 M1.93@688.98,1239.21 ; v1@374.14,1234.86 cw(c384.14,1224.86) 384.14,1239 cw(c384.14,1253.14) v1@374.14,1243.14 ; 631.28,1239 ccw(c631.28,1275.25) M1.93@656.92,1249.62 ; 632.31,1239 cw(c632.31,1204.2) M1.93@656.92,1228.81 ; 645.77,1239 ccw(c645.77,1260.77) M1.93@661.16,1245.38 ; 646.79,1239 cw(c646.79,1218.68) M1.93@661.16,1233.05
  Bottom Layer w6: J3.36@150,608.27 217,675.27 217,768.06 276,827.06 276,1145 v1(370,1239) ; J3.36@150,624.76 ccw(c150,664.59) 178.16,636.43 ccw(c206.32,608.27) J3.36@166.5,608.27 ; J3.36@150,630.76 ccw(c150,685.07) 188.4,646.67 ccw(c226.81,608.27) J3.36@172.5,608.27 ; J3.36@150,636.76 ccw(c150,705.56) 198.65,656.91 ccw(c247.29,608.27) J3.36@178.5,608.27 ; v1@364.14,1239 cw(c350,1239) 360,1229 cw(c370,1219) v1@370,1233.14
WL_WAKE_AP: J4.10 M1.9 | length 2005.7
  Top Layer w6: M1.9@1172.86,1026.98 ccw(c1145.97,1053.87) 1184,1053.87 ; M1.9@1177.1,1022.74 ccw(c1160.46,1039.39) 1184,1039.39 ; v1@1179.86,1061.86 cw(c1169.86,1051.86) 1184,1051.86 cw(c1198.14,1051.86) v1@1188.14,1061.86 ; M1.9@1183.27,994.92 1184,995.65 v1(1184,1066) ; 1184,1035.85 ccw(c1202.54,1035.85) M1.9@1189.43,1022.74 ; 1184,1050.34 ccw(c1217.03,1050.34) M1.9@1193.67,1026.98
  Bottom Layer w6: v1@1184,1060.14 cw(c1184,1046) 1194,1056 cw(c1204,1066) v1@1189.86,1066 ; v1(1184,1066) 1204,1046 2424.03,1046 2509.8,960.23 2509.8,865 J4.10@2566.54,808.27 ; J4.10@2538.04,808.27 ccw(c2469.24,808.27) 2517.89,856.91 ccw(c2566.54,905.56) J4.10@2566.54,836.76 ; J4.10@2544.04,808.27 ccw(c2489.73,808.27) 2528.13,846.67 ccw(c2566.54,885.07) J4.10@2566.54,830.76 ; J4.10@2550.04,808.27 ccw(c2510.21,808.27) 2538.37,836.43 ccw(c2566.54,864.59) J4.10@2566.54,824.76
XIN: R37.2 U3.20 | length 224.3
  Top Layer w6: R37.2@1653.69,769.39 cw(c1607.57,723.26) 1672.8,723.26 ; R37.2@1657.93,773.63 cw(c1622.05,737.75) 1672.8,737.75 ; R37.2@1659.92,775.62 1672.8,762.74 ; R37.2@1660.94,766.87 cw(c1662.61,752.56) 1672.79,762.74 ; R37.2@1662.18,777.87 cw(c1636.54,752.24) 1672.8,752.24 ; R37.2@1668.67,774.6 ccw(c1682.98,772.93) 1672.79,762.74 ; U3.20@1672.8,702.13 1672.8,762.74
XOUT: C33.2 U3.21 X1.3 | length 381.4
  Top Layer w6: C33.2@1614.27,768.86 cw(c1604.13,756.75) 1619.92,756.75 ; C33.2@1619.92,775.62 1619.92,756.75 ; C33.2@1625.58,768.86 ccw(c1635.71,756.75) 1619.92,756.75 ; v1@1628.72,742.09 ccw(c1614.58,742.09) 1624.58,752.09 ccw(c1634.58,762.09) v1@1634.58,747.95 ; v1@1634.58,736.23 cw(c1634.58,722.09) 1644.58,732.09 cw(c1654.58,742.09) v1@1640.44,742.09 ; U3.21@1657.05,702.13 1657.05,719.63 v1(1634.58,742.09) 1619.92,756.75
  Bottom Layer w6: X1.3@1614.35,768.59 cw(c1610.94,745.19) v1@1634.58,745.19 ; X1.3@1615.21,774.53 cw(c1611.95,752.13) 1634.58,752.13 ; X1.3@1616.07,780.46 cw(c1612.96,759.07) 1634.58,759.07 ; X1.3@1616.45,787 1634.58,768.86 v1(1634.58,742.09) ; X1.3@1616.94,786.4 cw(c1613.97,766) X1.3@1634.58,766 ; v1@1629.87,745.57 ccw(c1620.32,752.6) 1631.78,755.67 ; v1@1630.44,746.23 ccw(c1620.44,756.23) 1634.58,756.23 ccw(c1648.73,756.23) v1@1638.72,746.23 ; 1632.2,754.09 ccw(c1643.21,757.04) v1@1637.51,747.16
pads on no net: DEBUG. DEBUG.A8 DEBUG.B8 FEL. J1.14 J1.15 J3.10 J3.12 J3.16 J3.18 J3.22 J3.23 J3.24 J3.26 J3.28 J4.18 J4.32 J4.38 J4.40 OTG. OTG.A8 OTG.B8 RESET. U3.12 U3.13 U3.16 U3.22 U3.26 U3.27 U3.28

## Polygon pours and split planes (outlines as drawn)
VCC_5V on PWR "PWR_VCC_5V" (solid, remove dead copper, pour order 6): 0,1275 55,1275 1145,1275 1150,1270 1160,1260 1160,1240 1160,885 1180,865 1373,672 1373,618 1373,502 1390,485 1400,475 1470,475 2110,475 2140,505 2170,535 2265,630 2685,630 2716.54,630 2716.54,620 2716.54,0 2625,0 0,0 0,10 0,1275
SYS_3V3 on PWR "PWR_SYS_3V3" (solid, remove dead copper, pour order 7): 0,2716.54 2716.54,2716.54 2716.54,2695 2716.54,0 2680,0 0,0 0,20 0,2716.54
GND on GND "GND_GND" (solid, remove dead copper, pour order 10): 0,2716.54 80,2716.54 2716.54,2716.54 2716.54,2695 2716.54,0 2670,0 0,0 0,2716.54
GND on Top Layer "TOP_GND" (solid, remove dead copper, pour order 9): 0,2716.54 80,2716.54 2716.54,2716.54 2716.54,2695 2716.54,0 2670,0 0,0 0,2716.54
GND on Bottom Layer "BOTTOM_GND" (solid, remove dead copper, pour order 8): 0,2716.54 80,2716.54 2716.54,2716.54 2716.54,2695 2716.54,0 2670,0 0,0 0,2716.54

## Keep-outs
Keep-Out Layer:
  the board outline again, w5.98

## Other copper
Top Layer:
  region net AVDDRF: 1838.58,472.09 1915.58,395.09 1960.58,395.09 1960.58,333.09 1891.58,333.09 1886.58,338.09 1886.58,375.09 1813.58,448.09 1782.58,448.09 1782.58,472.09
  region net USB_OTG_VBUS: 1278.58,401.09 1281.58,398.09 1281.58,370.09 1278.58,367.09 1196.58,367.09 1191.58,372.09 1191.58,401.09
  region net USB_OTG_VBUS: 830,446 882,446 887,441 887,401 897,391 967,391 967,376 957,366 830,366
  region net VCC_5V: 765,970 901,970 901,953 954,900 954,831 950,827 811,827 765,873
  region net GND: 950.58,350.09 943.58,357.09 866.58,357.09 852.58,343.09 852.58,65.09 856.58,61.09 913.58,61.09 920.58,68.09 920.58,268.09 926.58,274.09 950.58,274.09
  region net GND: 1179.58,327.09 1198.58,346.09 1446.58,346.09 1450.58,342.09 1450.58,271.09 1424.58,271.09 1420.58,267.09 1420.58,68.09 1412.58,60.09 1223.58,60.09 1214.58,69.09 1214.58,134.09 1232.58,152.09 1232.58,214.09 1214.58,232.09 1214.58,267.09 1207.58,274.09 1179.58,274.09
  region net GND: 1764.58,359.09 1772.58,367.09 1826.58,367.09 1870.58,323.09 1870.58,97.09 1837.58,64.09 1805.58,64.09 1800.58,69.09 1800.58,266.09 1794.58,272.09 1764.58,272.09
  pour cut-out: 1853.58,546.09 2008.58,546.09 2018.58,536.09 2018.58,361.09 2008.58,351.09 1853.58,351.09 1843.58,361.09 1843.58,536.09
  region net SYS_3V3: 2335,323 2344,332 2383,332 2391,340 2391,489 2301,579 2223,579 2221,581 2221,642 2222,643 2367,643 2465,545 2465,371 2492,344 2618,344 2633,359 2633,440 2699,440 2699,316 2677,294 2466,294 2441,269 2441,249 2432,240 2218,240 2210,248 2210,323
  region net VCC_5V: 2090,391 2092,389 2092,332 2107,317 2107,240 2101,234 2033,234 2025,242 2025,391
  region net NetL1_1: 2070,524 2048,546 2048,642 2111,642 2111,536 2090,515 2090,433 2070,433
  region net GND: 1446.58,346.09 1447.67,345 1526,345 1535,336 1535,294 1505,264 1505,66 1499.09,60.09 1410.91,60.09 1402,69 1402,310 1438.09,346.09
  region net GND: 2380,470 2334,516 2120,516 2107,503 2107,433 2127,433 2127,487 2134,494 2232,494 2254,472 2254,423 2255,422 2287,422 2300,409 2300,338 2328.44,338 2345.44,355 2380,355
  region net GND: 2193,326 2197,322 2197,223 2191,217 2133,217 2122,228 2122,326
  region net SYS_3V3: 2221,805 2358,805 2387,776 2387,622 2368,603 2229.5,603 2221,611.5
  pour cut-out: 2265,700 2265,525 2250,525 2249,524 2070,524 2070,700
Bottom Layer:
  region net USB_OTG_VBUS: 939,422 911,450 850,450 839,439 839,380 855,364 952,364 965,377 965,397 944,418
  region net USB_OTG_VBUS: 1352,398 1318,364 1233,364 1227,370 1227,402 1229,404 1266,404 1277,415 1277,477 1352,477
  region net BL702_VBUS: 1413.58,376.09 1406.58,369.09 1357.58,369.09 1357.58,317.09 1436.58,317.09 1454.58,335.09 1755.58,335.09 1758.58,338.09 1758.58,381.09 1753.58,386.09 1496.58,386.09 1486.58,396.09 1486.58,476.09 1413.58,476.09
  region net GND: 902,1170 828,1170 747,1089 747,1048 902,1048
  region net VCC_5V: 787,1033 968,1033 968,1012 1023,957 1310,957 1345,922 1345,720 1410,655 1474,655 1488,641 1488,554 1487,553 1212,553 1166,599 1166,767 1106,827 818,827 806,839 806,934 787,953

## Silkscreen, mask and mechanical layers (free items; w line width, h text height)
Top Overlay:
  lines w5.98: 816,564 816,798 ; 1234.88,357.18 1235.97,356.09
  lines w6: 200,358.27 342.53,358.27 344.4,358.27 ; 200,2358.27 344.27,2358.27 ; 2337,399 2330,399 2318,411 2318,724 2317,725 2229,725 2229,2357 2230,2358 2270,2358 2270.27,2358.27 2516.54,2358.27 ; 2378,2356 2378,921 2378,865 2380,863 2418,863 2418,404 2413,399 ; 2387,399 2413,399 ; 2516.54,358.27 2453.73,358.27 2413,399 ; 344.27,2358.27 344.4,2358.4 344.4,1789 344.4,358.27 ; 344.27,2358.27 479.73,2358.27 479.73,361.73 476.27,358.27 344.4,358.27
  lines w8: 928,375 673,375 663.09,384.91 663.09,473.09 954.58,473.09
  text "NC" at 2241,2293 h30
  text "5V" at 358,2292 h30
  text "GND" at 2432,2291 h30
  text "3.3V" at 214,2290 h30
  text "NC" at 2239,2195 h30
  text "PB4" at 2432,2195 h30
  text "TP_X1" at 215,2189 h30
  text "5V" at 357,2189 h30
  text "PB5" at 2243,2097 h30
  text "PB6" at 2434,2097 h30
  text "GND" at 353,2095 h30
  text "TP_X2" at 215,2094 h30
  text "PB7" at 2435,1995 h30
  text "GND" at 2242,1994 h30
  text "TP_Y1" at 212,1993 h30
  text "TP_Y2" at 352,1993 h30
  text "NC" at 2246,1897 h30
  text "GND" at 213,1896 h30
  text "PE1" at 2441,1896 h30
  text "NC" at 357,1894 h30
  text "PE0" at 2437,1801 h30
  text "GND" at 2240,1800 h30
  text "TVOUT" at 206,1794 h30
  text "NC" at 359,1794 h30
  text "TVIN0" at 210,1699 h30
  text "GND" at 354,1698 h30
  text "PE4" at 2238,1695 h30
  text "PE5" at 2436,1695 h30
  text "TVIN1" at 210,1600 h30
  text "GND" at 2429,1598 h30
  text "NC" at 358,1597 h30
  text "PE6" at 2241,1595 h30
  text "NC" at 356,1496 h30
  text "PE8" at 2436,1496 h30
  text "PE7" at 2242,1494 h30
  text "3.3V" at 211,1493 h30
  text "GND" at 359,1400 h30
  text "DP" at 212,1398 h30
  text "PE10" at 2417,1393 h30
  text "PE9" at 2241,1392 h30
  text "NC" at 364,1304 h30
  text "DM" at 209,1300 h30
  text "GND" at 2240,1297 h30
  text "PE11" at 2424,1296 h30
  text "3.3V" at 2420,1202 h30
  text "NC" at 363,1201 h30
  text "NC" at 212,1200 h30
  text "NC" at 2241,1198 h30
  text "NC" at 361,1103 h30
  text "GND" at 211,1096 h30
  text "PE2" at 2241,1092 h30
  text "PE3" at 2433,1092 h30
  text "GND" at 2238,996 h30
  text "RESET" at 2392,996 h30
  text "PG1" at 211,991 h30
  text "NC" at 363,990 h30
  text "GND" at 350,899 h30
  text "PG11" at 2421,898 h30
  text "PG2" at 212,896 h30
  text "AP24M" at 2232,895 h30
  text "PG0" at 209,795 h30
  text "PG10" at 2242,795 h30
  text "GND" at 2432,795 h30
  text "PG3" at 354,791 h30
  text "PG5" at 210,696 h30
  text "GND" at 357,695 h30
  text "PG9" at 2330,695 h30
  text "PG8" at 2433,694 h30
  text "PG4" at 211,596 h30
  text "PG12" at 360,594 h30
  text "PG7" at 2430,592 h30
  text "GND" at 2327,591 h30
  text "PG13" at 210,498 h30
  text "PG6" at 2433,497 h30
  text "PG14" at 358,496 h30
  text "5V" at 2331,496 h30
  text "3.3V" at 2424,404 h30
  text "5V" at 2334,402 h30
  text "GND" at 211,392 h30
  text "PG15" at 358,389 h30
Bottom Overlay:
  drawing of 1465 lines, arcs and shapes, not listed
  text "PB3" at 1302,2451 h30 r270
  text "PD6" at 1856,2451 h30 r270
  text "PD8" at 1775,2450 h30 r270
  text "PD4" at 1932,2450 h30 r270
  text "PD2" at 2012,2448 h30 r270
  text "PD0" at 2091,2447 h30 r270
  text "GND" at 595,2436 h30 r270
  text "3.3V" at 669,2434 h30 r270
  text "PE12" at 1225,2433 h30 r270
  text "PD19" at 1147,2429 h30 r270
  text "PD16" at 1461,2428 h30 r270
  text "PD14" at 1542,2426 h30 r270
  text "PD12" at 1619,2426 h30 r270
  text "PD22" at 1380,2425 h30 r270
  text "PD10" at 1697,2425 h30 r270
  text "PD20" at 1068,2423 h30 r270
  text "LINEINR" at 987,2388 h30 r270
  text "MICIN_P" at 908,2372 h30 r270
  text "HPOUTR" at 834,2363 h30 r270
  text "HPOUTFB" at 752,2344 h30 r270
  text "5V" at 745,2270 h30 r270
  text "PD1" at 2087,2260 h30 r270
  text "PD9" at 1770,2254 h30 r270
  text "PD7" at 1845,2251 h30 r270
  text "PD5" at 1926,2251 h30 r270
  text "GND" at 667,2250 h30 r270
  text "PD3" at 2008,2250 h30 r270
  text "GND" at 593,2249 h30 r270
  text "PB2" at 1300,2245 h30 r270
  text "PD11" at 1692,2242 h30 r270
  text "PD17" at 1457,2231 h30 r270
  text "PD15" at 1536,2231 h30 r270
  text "PD13" at 1619,2231 h30 r270
  text "PD21" at 1149,2229 h30 r270
  text "PE13" at 1224,2229 h30 r270
  text "PD18" at 1070,2227 h30 r270
  text "RESET" at 1374,2202 h30 r270
  text "LINEINL" at 988,2191 h30 r270
  text "MICIN_N" at 909,2174 h30 r270
  text "HPOUTL" at 832,2172 h30 r270
  text "DongshanPi-D1s" at 2191,1971 h150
